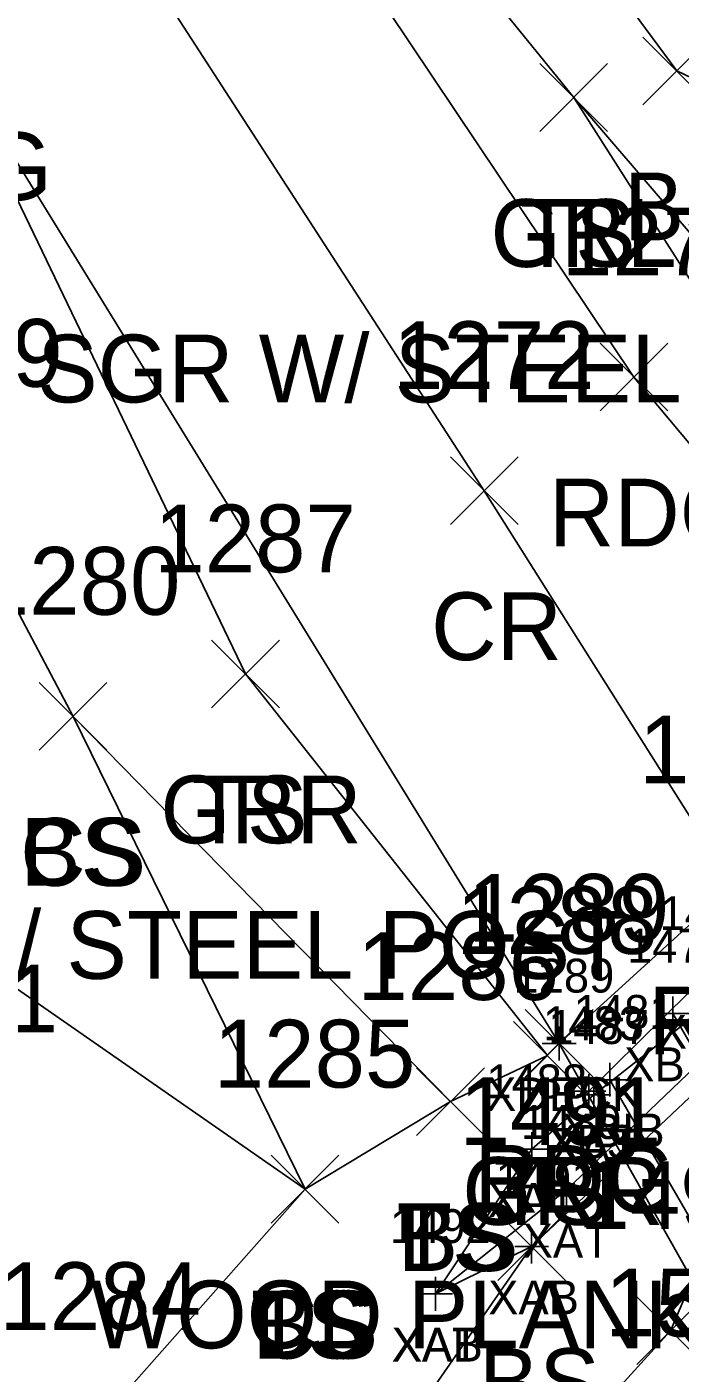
# Model space of a CAD drawing. Extents: x 1441651 to 1442140, y 243798 to 245625.
# Drawn here: x 1442027.42 to 1442046.7, y 245404.9 to 245444.63 of the extents above; entities that cross this region are included whole.
import ezdxf

# ---------------------------------------------------------------- set-up
doc = ezdxf.new("R2010")
doc.units = 0
for name, color, linetype in [('B_A', 7, 'Continuous'), ('B_I', 7, 'Continuous'), ('B_TIC', 7, 'Continuous'), ('BB', 7, 'Continuous'), ('BELB', 7, 'Continuous'), ('BSE', 7, 'Continuous'), ('BSUBM', 7, 'Continuous'), ('L_A', 7, 'Continuous'), ('L_I', 7, 'Continuous'), ('L_TIC', 7, 'Continuous'), ('LAWE', 7, 'Continuous'), ('LELB', 7, 'Continuous'), ('P_A', 7, 'Continuous'), ('P_C', 7, 'Continuous'), ('P_I', 7, 'Continuous'), ('P_TIC', 7, 'Continuous'), ('PEU', 7, 'Continuous'), ('PRC', 7, 'Continuous'), ('R_A', 7, 'Continuous'), ('R_C', 7, 'Continuous'), ('R_I', 7, 'Continuous'), ('R_TIC', 7, 'Continuous'), ('RGR', 7, 'Continuous')]:
    doc.layers.add(name, color=color, linetype=linetype)

msp = doc.modelspace()

# ---------------------------------------------------------------- linework, layer by layer
at = {"layer": 'B_TIC'}
for p, q in [((1442046.486, 245415.511), (1442046.562, 245415.511)), ((1442043.138, 245414.629), (1442043.213, 245414.629)), ((1442044.63, 245413.558), (1442044.706, 245413.558)), ((1442044.009, 245413.221), (1442044.085, 245413.221)), ((1442044.16, 245413.11), (1442044.235, 245413.11)), ((1442042.332, 245411.507), (1442042.407, 245411.507)), ((1442043.356, 245410.307), (1442043.432, 245410.307)), ((1442042.323, 245408.629), (1442042.399, 245408.629)), ((1442039.486, 245407.236), (1442039.562, 245407.236)), ((1442039.486, 245407.236), (1442039.562, 245407.236)), ((1442039.486, 245407.236), (1442039.562, 245407.236))]:
    msp.add_line(p, q, dxfattribs=at)
for points in [[(1442046.483, 245415.011), (1442046.483, 245416.011)], [(1442045.983, 245415.511), (1442046.983, 245415.511)], [(1442043.134, 245414.129), (1442043.134, 245415.129)], [(1442042.634, 245414.629), (1442043.634, 245414.629)], [(1442044.627, 245413.058), (1442044.627, 245414.058)], [(1442044.006, 245412.721), (1442044.006, 245413.721)], [(1442044.127, 245413.558), (1442045.127, 245413.558)], [(1442044.156, 245412.61), (1442044.156, 245413.61)], [(1442043.506, 245413.221), (1442044.506, 245413.221)], [(1442043.656, 245413.11), (1442044.656, 245413.11)], [(1442042.328, 245411.007), (1442042.328, 245412.007)], [(1442041.828, 245411.507), (1442042.828, 245411.507)], [(1442043.353, 245409.807), (1442043.353, 245410.807)], [(1442042.853, 245410.307), (1442043.853, 245410.307)], [(1442042.32, 245408.129), (1442042.32, 245409.129)], [(1442041.82, 245408.629), (1442042.82, 245408.629)], [(1442039.483, 245406.736), (1442039.483, 245407.736)], [(1442039.483, 245406.736), (1442039.483, 245407.736)], [(1442039.483, 245406.736), (1442039.483, 245407.736)], [(1442038.983, 245407.236), (1442039.983, 245407.236)], [(1442038.983, 245407.236), (1442039.983, 245407.236)], [(1442038.983, 245407.236), (1442039.983, 245407.236)]]:
    msp.add_lwpolyline(points, dxfattribs=at)
at = {"layer": 'BB'}
for points in [[(1442057.367, 245396.683), (1442046.483, 245415.511)], [(1442044.627, 245413.558), (1442055.528, 245394.741)]]:
    msp.add_lwpolyline(points, dxfattribs=at)
at = {"layer": 'BELB'}
msp.add_lwpolyline([(1442043.134, 245414.629), (1442055.546, 245392.581)], dxfattribs=at)
at = {"layer": 'BSE'}
msp.add_lwpolyline([(1442055.116, 245424.178), (1442044.006, 245413.221)], dxfattribs=at)
at = {"layer": 'BSUBM'}
for points in [[(1442059.882, 245434.236), (1442060.401, 245434.055), (1442057.354, 245424.964), (1442050.715, 245417.356), (1442043.353, 245410.307), (1442039.483, 245407.236)], [(1442050.199, 245417.857), (1442044.156, 245413.11), (1442042.328, 245411.507), (1442039.483, 245407.236)], [(1442050.947, 245416.77), (1442042.32, 245408.629), (1442039.483, 245407.236)]]:
    msp.add_lwpolyline(points, dxfattribs=at)
at = {"layer": 'L_TIC'}
for points in [[(1442045.602, 245442.334), (1442047.602, 245444.334)], [(1442047.602, 245442.334), (1442045.602, 245444.334)], [(1442042.563, 245441.549), (1442044.563, 245443.549)], [(1442044.563, 245441.549), (1442042.563, 245443.549)], [(1442032.876, 245424.535), (1442034.876, 245426.535)], [(1442034.876, 245424.535), (1442032.876, 245426.535)], [(1442027.785, 245423.281), (1442029.785, 245425.281)], [(1442029.785, 245423.281), (1442027.785, 245425.281)], [(1442027.785, 245423.281), (1442029.785, 245425.281)], [(1442029.785, 245423.281), (1442027.785, 245425.281)], [(1442041.785, 245413.272), (1442043.785, 245415.272)], [(1442043.785, 245413.272), (1442041.785, 245415.272)], [(1442038.926, 245411.912), (1442040.926, 245413.912)], [(1442040.926, 245411.912), (1442038.926, 245413.912)], [(1442038.926, 245411.912), (1442040.926, 245413.912)], [(1442040.926, 245411.912), (1442038.926, 245413.912)], [(1442034.632, 245409.326), (1442036.632, 245411.326)], [(1442036.632, 245409.326), (1442034.632, 245411.326)], [(1442034.632, 245409.326), (1442036.632, 245411.326)], [(1442036.632, 245409.326), (1442034.632, 245411.326)], [(1442034.632, 245409.326), (1442036.632, 245411.326)], [(1442036.632, 245409.326), (1442034.632, 245411.326)], [(1442041.32, 245407.629), (1442043.32, 245409.629)], [(1442043.32, 245407.629), (1442041.32, 245409.629)], [(1442045.422, 245405.149), (1442047.422, 245407.149)], [(1442047.422, 245405.149), (1442045.422, 245407.149)]]:
    msp.add_lwpolyline(points, dxfattribs=at)
at = {"layer": 'LAWE'}
msp.add_lwpolyline([(1442099.331, 245492.7), (1442082.175, 245474.825), (1442073.962, 245459.556), (1442071.044, 245454.669), (1442067.5, 245447.08), (1442064.769, 245439.016), (1442060.82, 245433.995), (1442057.711, 245424.573), (1442056.016, 245422.421), (1442050.947, 245416.77), (1442046.422, 245406.149), (1442038.474, 245397.39), (1442032.995, 245390.022), (1442022.028, 245379.959), (1442015.438, 245373.014), (1442011.82, 245364.946), (1441999.311, 245341.928), (1441993.277, 245326.588), (1441983.696, 245301.797)], dxfattribs=at)
at = {"layer": 'LELB'}
for points in [[(1441958.143, 245603.853), (1441973.054, 245572.702), (1441987.155, 245544.678), (1442001.278, 245515.813), (1442017.222, 245492.134), (1442028.726, 245467.165), (1442040.19, 245452.018), (1442046.602, 245443.334), (1442055.536, 245439.064), (1442059.345, 245437.756)], [(1441951.999, 245600.361), (1441967.384, 245569.64), (1441982.753, 245541.997), (1441998.178, 245514.398), (1442013.668, 245490.085), (1442025.646, 245464.596), (1442043.563, 245442.549), (1442056.061, 245427.98)], [(1441923.447, 245583.224), (1441912.774, 245568.104), (1441914.394, 245547.708), (1441930.794, 245525.129), (1441946.539, 245502.48), (1441950.678, 245491.319), (1441947.348, 245479.457), (1441950.826, 245463.211), (1441954.445, 245457.195), (1441962.212, 245455.423), (1441972.577, 245437.756), (1441995.951, 245413.456), (1442007.462, 245408.084), (1442021.352, 245397.079), (1442029.302, 245403.168), (1442035.632, 245410.326), (1442039.926, 245412.912), (1442042.785, 245414.272)], [(1442010.283, 245460.761), (1442024.733, 245444.52), (1442033.876, 245425.535)], [(1442004.083, 245459.771), (1442021.867, 245442.546), (1442025.23, 245431.01), (1442028.785, 245424.281), (1442039.926, 245412.912)], [(1441988.429, 245451.226), (1442003.87, 245434.808), (1442025.23, 245431.01), (1442028.785, 245424.281), (1442035.632, 245410.326)], [(1441982.227, 245444.744), (1442002.268, 245431.797), (1442015.267, 245424.484), (1442035.632, 245410.326)], [(1442042.32, 245408.629), (1442034.081, 245396.771), (1442024.361, 245389.769)]]:
    msp.add_lwpolyline(points, dxfattribs=at)
at = {"layer": 'P_TIC'}
for points in [[(1442044.339, 245433.299), (1442046.339, 245435.299)], [(1442046.339, 245433.299), (1442044.339, 245435.299)], [(1442039.921, 245429.942), (1442041.921, 245431.942)], [(1442041.921, 245429.942), (1442039.921, 245431.942)], [(1442042.134, 245413.629), (1442044.134, 245415.629)], [(1442044.134, 245413.629), (1442042.134, 245415.629)]]:
    msp.add_lwpolyline(points, dxfattribs=at)
at = {"layer": 'PEU'}
for points in [[(1441949.699, 245598.806), (1441965.584, 245568.638), (1441979.812, 245540.541), (1441994.499, 245512.774), (1442011.015, 245488.252), (1442024.854, 245464.866), (1442045.339, 245434.299), (1442053.641, 245424.38)], [(1441937.939, 245591.884), (1441953.89, 245562.719), (1441968.906, 245535.694), (1441984.797, 245506.977), (1441992.987, 245492.297), (1442013.076, 245458.975), (1442024.733, 245444.52), (1442043.134, 245414.629), (1442048.272, 245419.302), (1442053.641, 245424.38)]]:
    msp.add_lwpolyline(points, dxfattribs=at)
at = {"layer": 'PRC'}
msp.add_lwpolyline([(1441943.372, 245595.219), (1441959.061, 245565.314), (1441973.709, 245538.049), (1441989.919, 245509.625), (1442005.514, 245485.136), (1442020.379, 245462.654), (1442040.921, 245430.942), (1442048.272, 245419.302)], dxfattribs=at)
at = {"layer": 'R_TIC'}
for points in [[(1442042.563, 245441.549), (1442044.563, 245443.549)], [(1442044.563, 245441.549), (1442042.563, 245443.549)], [(1442032.876, 245424.535), (1442034.876, 245426.535)], [(1442034.876, 245424.535), (1442032.876, 245426.535)], [(1442041.785, 245413.272), (1442043.785, 245415.272)], [(1442043.785, 245413.272), (1442041.785, 245415.272)]]:
    msp.add_lwpolyline(points, dxfattribs=at)
at = {"layer": 'RGR'}
for points in [[(1442043.563, 245442.549), (1442054.448, 245425.49)], [(1442033.876, 245425.535), (1442042.785, 245414.272)]]:
    msp.add_lwpolyline(points, dxfattribs=at)

# ---------------------------------------------------------------- texts
at = {"layer": 'B_A'}
for s, p in [('XBIB', (1442046.017, 245414.472)), ('XBIB', (1442045.054, 245413.511)), ('XDECK', (1442040.977, 245412.629)), ('XBS', (1442042.746, 245411.221)), ('XBIB', (1442043.198, 245411.558)), ('XAT', (1442042.861, 245411.11)), ('XAT', (1442041.033, 245409.507)), ('XAT', (1442042.057, 245408.307)), ('XAB', (1442041.04, 245406.629)), ('XAT', (1442038.188, 245405.236)), ('XAT', (1442038.188, 245405.236)), ('XAB', (1442038.203, 245405.236))]:
    msp.add_text(s, height=1, dxfattribs=at).set_placement(p)
at = {"layer": 'B_I'}
for s, p in [('1479', (1442046.096, 245417.972)), ('1478', (1442045.137, 245417.011)), ('1289', (1442041.784, 245416.129)), ('1481', (1442043.564, 245415.058)), ('1483', (1442042.659, 245414.721)), ('1487', (1442042.81, 245414.61)), ('1488', (1442040.982, 245413.007)), ('1489', (1442042.002, 245411.807)), ('1491', (1442041.257, 245410.129)), ('1492', (1442038.136, 245408.736)), ('1492', (1442038.136, 245408.736)), ('1492', (1442038.136, 245408.736))]:
    msp.add_text(s, height=1, dxfattribs=at).set_placement(p)
at = {"layer": 'L_A'}
for s, p in [('BS', (1442045.043, 245438.334)), ('TS', (1442041.973, 245437.549)), ('TS', (1442032.285, 245420.535)), ('CS', (1442027.226, 245419.281)), ('BS', (1442027.226, 245419.281)), ('TS', (1442041.194, 245409.272)), ('TS', (1442038.336, 245407.912)), ('BS', (1442038.367, 245407.912)), ('TS', (1442034.041, 245405.326)), ('CS', (1442034.073, 245405.326)), ('BS', (1442034.073, 245405.326)), ('BS', (1442040.761, 245403.629))]:
    msp.add_text(s, height=2, dxfattribs=at).set_placement(p)
at = {"layer": 'L_I'}
for s, p in [('1279', (1442022.53, 245434.01)), ('1279', (1442022.53, 245434.01)), ('1287', (1442031.183, 245428.535)), ('1280', (1442026.005, 245427.281)), ('1280', (1442026.005, 245427.281)), ('1288', (1442040.092, 245417.272)), ('1286', (1442037.178, 245415.912)), ('1286', (1442037.178, 245415.912)), ('1281', (1442022.392, 245414.952)), ('1285', (1442032.939, 245413.326)), ('1285', (1442032.939, 245413.326)), ('1285', (1442032.939, 245413.326)), ('1491', (1442040.194, 245411.629)), ('1493', (1442043.729, 245409.149)), ('1284', (1442026.609, 245406.168)), ('1505', (1442044.489, 245405.979))]:
    msp.add_text(s, height=2, dxfattribs=at).set_placement(p)
at = {"layer": 'P_A'}
for s, p in [('RDG', (1442022.221, 245439.52)), ('RDG', (1442042.827, 245429.299)), ('CR', (1442039.354, 245425.942)), ('RDG', (1442045.76, 245414.302)), ('RDG', (1442040.623, 245409.629))]:
    msp.add_text(s, height=2, dxfattribs=at).set_placement(p)
at = {"layer": 'P_C'}
msp.add_text('WOOD PLANK DECK', height=2, dxfattribs=at).set_placement((1442029.308, 245405.629))
at = {"layer": 'P_I'}
for s, p in [('1271', (1442043.213, 245437.299)), ('1272', (1442038.228, 245433.942)), ('1290', (1442045.492, 245422.302)), ('1290', (1442045.492, 245422.302)), ('1289', (1442040.434, 245417.629))]:
    msp.add_text(s, height=2, dxfattribs=at).set_placement(p)
at = {"layer": 'R_A'}
for s, p in [('GRL', (1442041.106, 245437.549)), ('GRR', (1442031.364, 245420.535)), ('GRR', (1442040.273, 245409.272))]:
    msp.add_text(s, height=2, dxfattribs=at).set_placement(p)
at = {"layer": 'R_C'}
for p in [(1442027.728, 245433.549), (1442018.041, 245416.535)]:
    msp.add_text('SGR W/ STEEL POST', height=2, dxfattribs=at).set_placement(p)
at = {"layer": 'R_I'}
for s, p in [('1287', (1442031.183, 245428.535)), ('1288', (1442040.092, 245417.272))]:
    msp.add_text(s, height=2, dxfattribs=at).set_placement(p)

doc.saveas('drawing.dxf')
